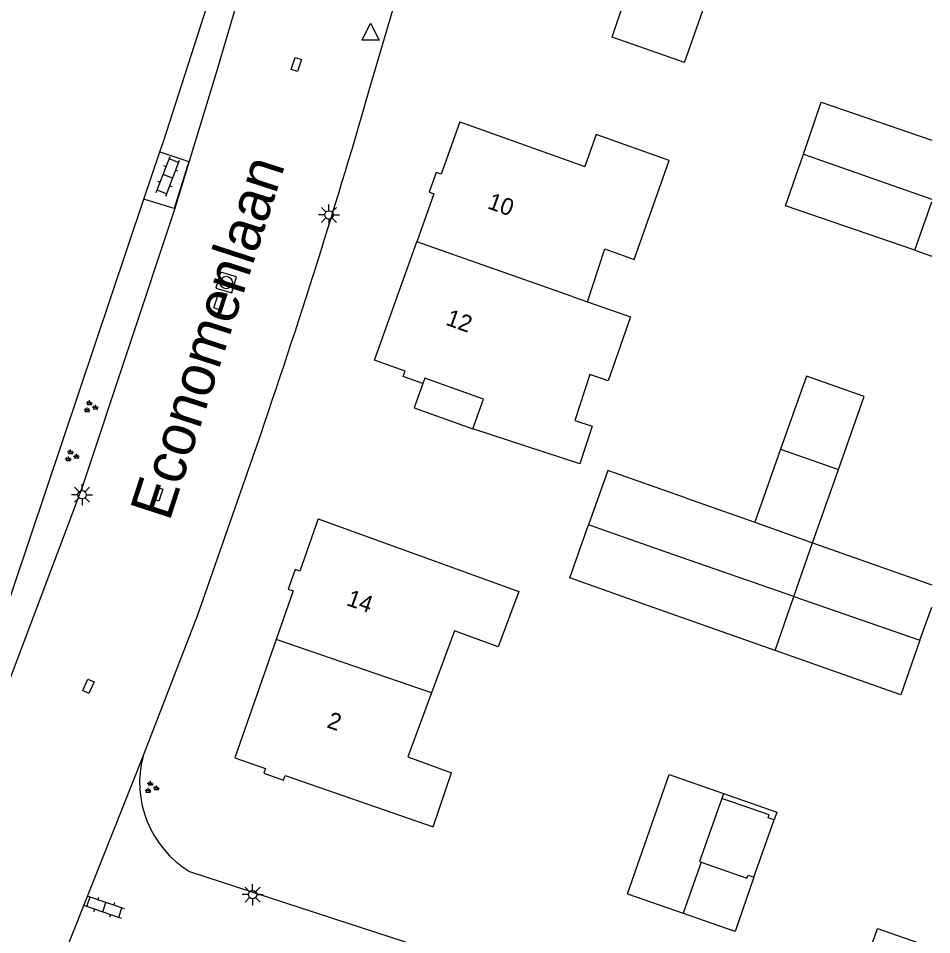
# Model space of a CAD drawing. Extents: x 128999 to 131010, y 395498 to 399007.
# Drawn here: x 130945.7 to 131000, y 396821 to 396875.4 of the extents above; entities that cross this region are included whole.
import ezdxf

# ---------------------------------------------------------------- set-up
doc = ezdxf.new("R2010")
doc.units = 0
for name, color, linetype in [('gg-afsc-erfafscheiding', 7, 'Continuous'), ('gg-afsc-muur', 7, 'Continuous'), ('gg-anno-huisnummerreeks BGT', 7, 'Continuous'), ('gg-anno-openbare ruimte label', 7, 'Continuous'), ('gg-bbg-bijgebouw', 7, 'Continuous'), ('gg-bbg-gedigitaliseerde bebouwing', 7, 'Continuous'), ('gg-bbg-gedigitaliseerde bijgebouw', 7, 'Continuous'), ('gg-bbg-hoofdgebouw', 7, 'Continuous'), ('gg-bbg-luifel en loopbrug', 7, 'Continuous'), ('gg-bbg-tussenscheiding', 7, 'Continuous'), ('gg-knt-verharding', 7, 'Continuous'), ('gt-grn-groengrens', 7, 'Continuous'), ('gt-grn-weggrens', 7, 'Continuous'), ('gt-symb-groenvak', 7, 'Continuous'), ('gt-symb-klinker verharding', 7, 'Continuous'), ('gt-symb-kolk center center', 7, 'Continuous'), ('gt-symb-lichtmast', 7, 'Continuous'), ('gt-symb-rioolschacht', 7, 'Continuous'), ('gt-symb-waterafsluiter', 7, 'Continuous')]:
    doc.layers.add(name, color=color, linetype=linetype)

# ---------------------------------------------------------------- blocks, each defined once
blk = doc.blocks.new('gt0-LMAST')
at = {"layer": 'gt-symb-lichtmast'}
for p, q in [((-0.005, 0.246), (-0.005, 0.621)), ((-0.182, 0.173), (-0.447, 0.438)), ((0.172, 0.173), (0.437, 0.438)), ((-0.255, -0.004), (-0.63, -0.004)), ((-0.182, -0.181), (-0.447, -0.446)), ((-0.005, -0.254), (-0.005, -0.629)), ((0.437, -0.446), (0.172, -0.181)), ((0.245, -0.004), (0.62, -0.004))]:
    blk.add_line(p, q, dxfattribs=at)
blk.add_circle((-0.005, -0.004), 0.25, dxfattribs=at)
blk = doc.blocks.new('gt0-KOLKCC')
at = {"layer": 'gt-symb-kolk center center'}
blk.add_lwpolyline([(-0.375, 0.2), (0.375, 0.2), (0.375, -0.2), (-0.375, -0.2)], close=True, dxfattribs=at)
blk = doc.blocks.new('gt0-RS')
at = {"layer": 'gt-symb-rioolschacht'}
blk.add_lwpolyline([(-0.5, -0.5), (0.5, -0.5), (0.5, 0.5), (-0.5, 0.5)], close=True, dxfattribs=at)
blk.add_circle((0, 0), 0.375, dxfattribs=at)
blk = doc.blocks.new('gt0-WAFSL')
at = {"layer": 'gt-symb-waterafsluiter'}
for p, q in [((-0.5, -0.333), (0, 0.667)), ((0, 0.667), (0.5, -0.333)), ((0.5, -0.333), (-0.5, -0.333))]:
    blk.add_line(p, q, dxfattribs=at)
blk = doc.blocks.new('gt0-GRVAK')
at = {"layer": 'gt-symb-groenvak'}
for p, q in [((-0.11, 0.189), (-0.228, 0.24)), ((-0.182, 0.153), (0.088, 0.153)), ((-0.091, 0.211), (-0.156, 0.322)), ((-0.047, 0.214), (-0.047, 0.393)), ((-0.004, 0.211), (0.061, 0.322)), ((0.015, 0.189), (0.133, 0.24)), ((0.262, -0.052), (0.197, 0.059)), ((0.305, -0.049), (0.305, 0.13)), ((0.349, -0.052), (0.414, 0.059)), ((-0.245, -0.228), (-0.363, -0.177)), ((-0.318, -0.264), (-0.047, -0.264)), ((-0.226, -0.206), (-0.291, -0.095)), ((-0.183, -0.203), (-0.183, -0.024)), ((-0.139, -0.206), (-0.074, -0.095)), ((-0.12, -0.228), (-0.002, -0.177)), ((0.243, -0.074), (0.125, -0.023)), ((0.17, -0.11), (0.441, -0.11)), ((0.368, -0.074), (0.486, -0.023))]:
    blk.add_line(p, q, dxfattribs=at)
blk = doc.blocks.new('gt0-KL1')
at = {"layer": 'gt-symb-klinker verharding'}
for p, q in [((-1.15, 0.3), (1.15, 0.3)), ((-1, -0.3), (-1, 0.3)), ((-0.5, 0.3), (-0.5, 0.45)), ((0, -0.3), (0, 0.3)), ((0.5, 0.3), (0.5, 0.45)), ((1, -0.3), (1, 0.3)), ((-1.15, -0.3), (1.15, -0.3)), ((-0.5, -0.45), (-0.5, -0.3)), ((0.5, -0.45), (0.5, -0.3))]:
    blk.add_line(p, q, dxfattribs=at)

msp = doc.modelspace()

# ---------------------------------------------------------------- linework, layer by layer
at = {"layer": 'gg-afsc-erfafscheiding'}
for p, q in [((130954.339, 396868.09), (130962.43, 396893.094)), ((130944.074, 396837.561), (130953.179, 396864.648))]:
    msp.add_line(p, q, dxfattribs=at)
at = {"layer": 'gg-afsc-muur'}
msp.add_lwpolyline([(130987.625, 396829.347), (130990.796, 396828.241), (130990.635, 396827.781)], dxfattribs=at)
at = {"layer": 'gg-bbg-bijgebouw'}
for p, q in [((130981.93, 396823.39), (130985.238, 396822.237)), ((130985.238, 396822.237), (130988.24, 396821.19))]:
    msp.add_line(p, q, dxfattribs=at)
for points in [[(130987.526, 396829.062), (130986.211, 396825.302), (130986.298, 396825.272)], [(130986.298, 396825.272), (130989.022, 396824.322), (130989.085, 396824.502), (130989.439, 396824.378)], [(130989.439, 396824.378), (130988.317, 396821.163), (130988.24, 396821.19)]]:
    msp.add_lwpolyline(points, dxfattribs=at)
at = {"layer": 'gg-bbg-gedigitaliseerde bebouwing'}
msp.add_line((130971.95, 396869.24), (130979.389, 396866.601), dxfattribs=at)
for points in [[(130985.31, 396872.77), (130987.233, 396878.235), (130984.561, 396879.186)], [(130979.538, 396858.566), (130980.566, 396861.699), (130982.322, 396861.076), (130984.404, 396866.946), (130980.069, 396868.499), (130979.389, 396866.601)], [(130979.538, 396858.566), (130982.093, 396857.674), (130980.766, 396853.873), (130979.688, 396854.249), (130978.789, 396851.509), (130979.822, 396851.169), (130979.088, 396848.932)], [(130963.54, 396845.67), (130975.456, 396841.357), (130974.24, 396838.058), (130971.64, 396839.016), (130970.279, 396835.325)], [(130970.279, 396835.325), (130968.877, 396831.522), (130971.46, 396830.57)]]:
    msp.add_lwpolyline(points, dxfattribs=at)
at = {"layer": 'gg-bbg-gedigitaliseerde bijgebouw'}
for p, q in [((130998.993, 396861.622), (131000, 396861.276)), ((130991.024, 396849.806), (130989.492, 396845.462)), ((130991.024, 396849.806), (130994.459, 396848.594)), ((130992.926, 396844.25), (130994.459, 396848.594)), ((130985.364, 396846.918), (130989.492, 396845.462)), ((130992.926, 396844.25), (131000, 396841.755)), ((130990.692, 396837.853), (130983.11, 396840.528)), ((130999.304, 396838.455), (131000, 396840.428))]:
    msp.add_line(p, q, dxfattribs=at)
for points in [[(130992.375, 396867.338), (130993.434, 396870.415), (131000, 396868.156)], [(130998.993, 396861.622), (130991.317, 396864.263), (130992.375, 396867.338)], [(130985.364, 396846.918), (130980.747, 396848.547), (130979.608, 396845.318)], [(130983.11, 396840.528), (130978.493, 396842.157), (130979.608, 396845.318)], [(130999.304, 396838.455), (130998.162, 396835.218), (130990.692, 396837.853)], [(130981.93, 396823.39), (130984.405, 396830.47), (130987.625, 396829.347)]]:
    msp.add_lwpolyline(points, dxfattribs=at)
at = {"layer": 'gg-bbg-hoofdgebouw'}
msp.add_line((130979.088, 396848.932), (130972.739, 396851.016), dxfattribs=at)
for points in [[(130985.31, 396872.77), (130981.007, 396874.284), (130981.708, 396876.347), (130977.248, 396877.844), (130977.147, 396877.562), (130975.98, 396877.98), (130976.09, 396878.29), (130974.25, 396878.93), (130976.767, 396886.134)], [(130971.95, 396869.24), (130970.84, 396866.143), (130970.558, 396866.244), (130970.14, 396865.077), (130970.422, 396864.976), (130969.403, 396862.131)], [(130969.763, 396853.708), (130968.595, 396854.125), (130968.706, 396854.436), (130966.88, 396855.09), (130969.403, 396862.131)], [(130972.739, 396851.016), (130973.367, 396852.767), (130969.874, 396854.019), (130969.763, 396853.708)], [(130963.54, 396845.67), (130962.455, 396842.564), (130962.172, 396842.663), (130961.763, 396841.493), (130962.046, 396841.394), (130961.036, 396838.501)], [(130961.036, 396838.501), (130958.58, 396831.47), (130960.413, 396830.835), (130960.315, 396830.552), (130961.487, 396830.146), (130961.585, 396830.429), (130970.38, 396827.38), (130971.46, 396830.57)], [(131000, 396815.372), (130995.283, 396817.019), (130996.785, 396821.322), (131000, 396820.209)]]:
    msp.add_lwpolyline(points, dxfattribs=at)
at = {"layer": 'gg-bbg-luifel en loopbrug'}
msp.add_line((130989.439, 396824.378), (130990.635, 396827.781), dxfattribs=at)
for points in [[(130994.459, 396848.594), (130995.991, 396852.938), (130992.557, 396854.15), (130991.024, 396849.806)], [(130969.763, 396853.708), (130969.247, 396852.268), (130972.739, 396851.016)], [(130990.635, 396827.781), (130990.281, 396827.904), (130990.345, 396828.088), (130987.526, 396829.062)]]:
    msp.add_lwpolyline(points, dxfattribs=at)
at = {"layer": 'gg-bbg-tussenscheiding'}
for p, q in [((130992.375, 396867.338), (131000, 396864.649)), ((130998.993, 396861.622), (131000, 396864.507)), ((130978.636, 396858.883), (130969.403, 396862.131)), ((130978.636, 396858.883), (130979.538, 396858.566)), ((130989.492, 396845.462), (130992.926, 396844.25)), ((130991.808, 396841.047), (130992.926, 396844.25)), ((130990.692, 396837.853), (130991.808, 396841.047)), ((130991.808, 396841.047), (130999.304, 396838.455)), ((130970.279, 396835.325), (130961.036, 396838.501)), ((130987.625, 396829.347), (130987.526, 396829.062)), ((130986.298, 396825.272), (130985.238, 396822.237))]:
    msp.add_line(p, q, dxfattribs=at)
msp.add_lwpolyline([(130991.808, 396841.047), (130984.225, 396843.689), (130979.608, 396845.318)], dxfattribs=at)
at = {"layer": 'gg-knt-verharding'}
msp.add_line((130966.577, 396871.124), (130970.364, 396883.989), dxfattribs=at)
for points in [[(130963.617, 396892.719), (130960.95, 396883.919), (130957.476, 396872.165), (130954.992, 396864.034), (130949.508, 396847.557), (130945.122, 396835.893)], [(130954.128, 396867.465), (130955.85, 396866.885), (130954.991, 396864.096), (130953.179, 396864.648)], [(130953.132, 396831.571), (130956.382, 396839.958), (130959.659, 396849.329)], [(130955.893, 396824.722), (130965.245, 396821.665), (130980.274, 396816.784), (130992.836, 396812.744), (131000, 396810.471)]]:
    msp.add_lwpolyline(points, dxfattribs=at)
for centre, radius, start, end in [((130544.421, 396993.126), 439.432, 340.89901, 343.88083), ((130959.124, 396830.005), 6.193, 165.3573, 238.5538)]:
    msp.add_arc(centre, radius, start, end, dxfattribs=at)
at = {"layer": 'gt-grn-groengrens'}
msp.add_line((130954.128, 396867.465), (130954.339, 396868.09), dxfattribs=at)
at = {"layer": 'gt-grn-weggrens'}
for p, q in [((130953.179, 396864.648), (130954.128, 396867.465)), ((130945.816, 396813.183), (130953.132, 396831.571))]:
    msp.add_line(p, q, dxfattribs=at)

# ---------------------------------------------------------------- block references
at = {"layer": 'gt-symb-groenvak'}
for p in [(130949.995, 396852.314), (130948.877, 396849.401), (130953.622, 396829.704)]:
    msp.add_blockref('gt0-GRVAK', p, dxfattribs=at)
at = {"layer": 'gt-symb-klinker verharding'}
for p, rotation in [((130954.61, 396866.011), 69.20927472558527), ((130950.834, 396822.602), -18.779117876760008)]:
    msp.add_blockref('gt0-KL1', p, dxfattribs=dict(at, rotation=rotation))
at = {"layer": 'gt-symb-kolk center center'}
for p, rotation in [((130962.246, 396872.652), -108.00007459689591), ((130957.65, 396858.486), 71.79726457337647), ((130953.996, 396847.126), 71.94544753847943), ((130949.883, 396835.723), 65.92116276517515)]:
    msp.add_blockref('gt0-KOLKCC', p, dxfattribs=dict(at, rotation=rotation))
at = {"layer": 'gt-symb-lichtmast'}
for p in [(130964.183, 396863.722), (130949.512, 396847.104), (130959.65, 396823.346)]:
    msp.add_blockref('gt0-LMAST', p, dxfattribs=at)
at = {"layer": 'gt-symb-rioolschacht', "rotation": 73.26783977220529}
msp.add_blockref('gt0-RS', (130958.073, 396859.706), dxfattribs=at)
at = {"layer": 'gt-symb-waterafsluiter'}
msp.add_blockref('gt0-WAFSL', (130966.656, 396874.434), dxfattribs=at)

# ---------------------------------------------------------------- texts
at = {"layer": 'gg-anno-huisnummerreeks BGT'}
for s, rotation, p in [('10', 340.3, (130973.542, 396864.127)), ('12', 340.3, (130971.064, 396857.21)), ('14', 340.7, (130965.166, 396840.552)), ('2', 340.9, (130964.002, 396833.295))]:
    msp.add_text(s, height=1, rotation=rotation, dxfattribs=at).set_placement(p)
at = {"layer": 'gg-anno-openbare ruimte label'}
msp.add_text('Economenlaan', height=2.5, rotation=72, dxfattribs=at).set_placement((130954.696, 396845.465))

doc.saveas('drawing.dxf')
